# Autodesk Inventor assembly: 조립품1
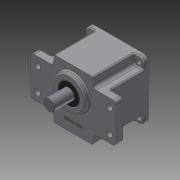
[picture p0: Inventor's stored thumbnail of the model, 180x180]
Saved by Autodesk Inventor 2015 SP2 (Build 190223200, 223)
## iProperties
Created: 2015-06
Part Number: 조립품1
Document SubType Name: Assembly
Designer: AMC
Author: AMC
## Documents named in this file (12)
- C:\Users\AMC\Desktop\450620V1010\조립품1.iam
- C:\Users\AMC\Desktop\450620V1010\본체.ipt
- C:\Users\AMC\Desktop\450620V1010\M4x0.5x16.ipt
- C:\Users\AMC\Desktop\450620V1010\메인축.ipt
- C:\Users\AMC\Desktop\450620V1010\베어링 608.ipt
- 베어링 608.ipt
- C:\Users\AMC\Desktop\450620V1010\베어링 6003.ipt
- 베어링 6003.ipt
- C:\Users\AMC\Desktop\450620V1010\서브축.ipt
- C:\Users\AMC\Desktop\450620V1010\오일실 8x22x7.ipt
- C:\Users\AMC\Desktop\450620V1010\오일실 17x32x8.ipt
- C:\Users\AMC\Desktop\450620V1010\커버.ipt
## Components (4 placed, 1 different names)
1. M4x0.5x12:1
2. M4x0.5x12:2
3. M4x0.5x12:3
4. M4x0.5x12:4
